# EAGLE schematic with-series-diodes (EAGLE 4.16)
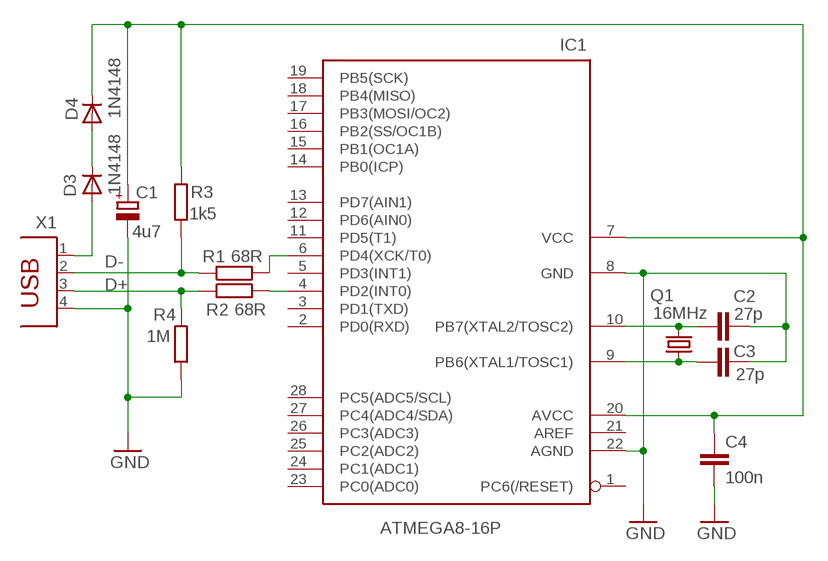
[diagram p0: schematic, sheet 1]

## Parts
C1  4u7  CPOL-EUE2-5  [E2-5]
C2  27p  C-EU025-024X044  [C025-024X044]
C3  27p  C-EU025-024X044  [C025-024X044]
C4  100n  C-EU025-024X044  [C025-024X044]
D3  1N4148  [DO35-10]
D4  1N4148  [DO35-10]
IC1  ATMEGA8-16P  [DIL28-3]
Q1  16MHz  CRYTALHC49U-V  [HC49U-V]
R1  68R  R-EU_0207/10  [0207/10]
R2  68R  R-EU_0207/10  [0207/10]
R3  1k5  R-EU_0207/10  [0207/10]
R4  1M  R-EU_0207/10  [0207/10]
X1  PN61729  [PN61729]

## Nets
D+: R2.1 R4.2 X1.3
D-: R1.1 R3.1 X1.2
GND: C1.- C2.2 C3.2 C4.2 IC1.8(GND) IC1.22(AGND) R4.1 X1.4
N$1: IC1.6(PD4(XCK/T0)) R1.2
N$2: IC1.4(PD2(INT0)) R2.2
N$3: D3.A X1.1
N$4: D3.C D4.A
N$9: C3.1 IC1.9(PB6(XTAL1/TOSC1)) Q1.1
N$10: C2.1 IC1.10(PB7(XTAL2/TOSC2)) Q1.2
VCC: C1.+ C4.1 D4.C IC1.7(VCC) IC1.20(AVCC) R3.2
Unconnected: IC1.1(PC6(/RESET)) IC1.2(PD0(RXD)) IC1.3(PD1(TXD)) IC1.5(PD3(INT1)) IC1.11(PD5(T1)) IC1.12(PD6(AIN0)) IC1.13(PD7(AIN1)) IC1.14(PB0(ICP)) IC1.15(PB1(OC1A)) IC1.16(PB2(SS/OC1B)) IC1.17(PB3(MOSI/OC2)) IC1.18(PB4(MISO)) IC1.19(PB5(SCK)) IC1.21(AREF) IC1.23(PC0(ADC0)) IC1.24(PC1(ADC1)) IC1.25(PC2(ADC2)) IC1.26(PC3(ADC3)) IC1.27(PC4(ADC4/SDA)) IC1.28(PC5(ADC5/SCL))

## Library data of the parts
C1 = rcl:CPOL-EU: POLARIZED CAPACITOR, European symbol
C2-C4 = rcl:C-EU: CAPACITOR, European symbol
D3 D4 = diode:1N4148: DIODE
IC1 = avr:ATMEGA8*P: MICROCONTROLLER 8 Kbytes FLASH 1 kbytes SRAM 512 bytes EEPROM USART 4-channel 10 bit ADC 2-channel 8 bit ADC
Q1 = crystal:CRYTAL: CRYSTAL
R1-R4 = rcl:R-EU_: RESISTOR, European symbol
X1 = con-berg:PN61729: BERG USB connector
